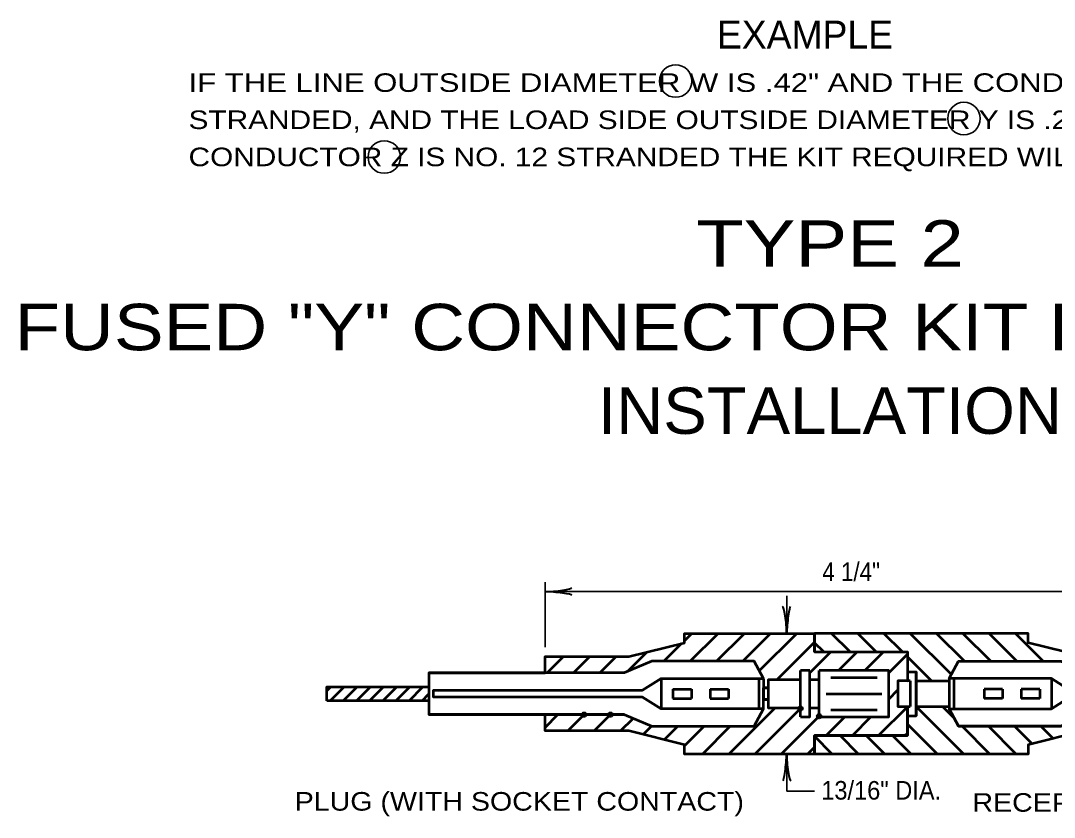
# Model space of a CAD drawing. Extents: x -1 to 679, y 0 to 440.
# Drawn here: x 256.4 to 367.7, y 153.2 to 239 of the extents above; entities that cross this region are included whole.
import ezdxf
from ezdxf.enums import TextEntityAlignment as Align

# ---------------------------------------------------------------- set-up
doc = ezdxf.new("R2010")
doc.units = 0
doc.header["$LTSCALE"] = 0.8
doc.header["$PDMODE"] = 32
doc.header["$PDSIZE"] = 0.4
doc.layers.add('1', color=7, linetype='Continuous', lineweight=53)

msp = doc.modelspace()

# ---------------------------------------------------------------- linework, layer by layer
at = {"layer": '1', "lineweight": 35}
for p, q in [((312.8991, 171.5513), (312.8991, 178.5513)), ((312.8991, 177.5513), (379.8991, 177.5513)), ((338.9009, 173.0513), (338.9009, 177.0949)), ((338.9009, 160.0513), (338.9009, 156.0513)), ((338.9009, 156.0513), (341.9009, 156.0513))]:
    msp.add_line(p, q, dxfattribs=at)
at = {"layer": '1'}
for p, q in [((327.8991, 172.2609), (328.6895, 173.0513)), ((328.5179, 170.0513), (331.5179, 173.0513)), ((331.3463, 170.0513), (334.3463, 173.0513)), ((334.1748, 170.0513), (337.1748, 173.0513)), ((335.9571, 169.0052), (340.0032, 173.0513)), ((341.8991, 171.0513), (341.8991, 173.0513)), ((345.7201, 171.0513), (343.7201, 173.0513)), ((348.5485, 171.0513), (346.5485, 173.0513)), ((351.3769, 171.0513), (349.3769, 173.0513)), ((356.6361, 168.6207), (352.2053, 173.0513)), ((358.0337, 170.0513), (355.0337, 173.0513)), ((360.8622, 170.0513), (357.8622, 173.0513)), ((363.6907, 170.0513), (360.6907, 173.0513)), ((366.5191, 170.0513), (363.5191, 173.0513)), ((325.6895, 170.0513), (327.6197, 171.9815)), ((337.8317, 168.0513), (341.8991, 172.1188)), ((342.8917, 171.0513), (341.8991, 172.0439)), ((313.1258, 168.8013), (314.8758, 170.5513)), ((315.9543, 168.8013), (317.7043, 170.5513)), ((318.7827, 168.8013), (320.5327, 170.5513)), ((321.7625, 168.9527), (323.8484, 171.0387)), ((341.3991, 168.7903), (343.6601, 171.0513)), ((344.4885, 169.0513), (346.4885, 171.0513)), ((347.3169, 169.0513), (349.3169, 171.0513)), ((349.8991, 168.8051), (351.8991, 170.8051)), ((354.5019, 167.9263), (351.8991, 170.5292)), ((300.3991, 168.8013), (300.3991, 164.3013)), ((325.3991, 168.1763), (325.3991, 164.9263)), ((335.8991, 168.1763), (335.8991, 164.9263)), ((336.3991, 168.1763), (336.3991, 165.9263)), ((336.3991, 168.1763), (336.3991, 165.9263)), ((340.3991, 164.0513), (340.3991, 169.0513)), ((341.3991, 169.0513), (340.3991, 169.0513)), ((340.3991, 164.0513), (340.3991, 169.0513)), ((341.3991, 169.0513), (340.3991, 169.0513)), ((342.3991, 168.0513), (341.3991, 168.0513)), ((342.3991, 168.0513), (341.3991, 168.0513)), ((342.3991, 164.0513), (342.3991, 169.0513)), ((342.3991, 164.0513), (342.3991, 169.0513)), ((343.6491, 168.3013), (348.6491, 168.3013)), ((356.3991, 168.1763), (356.3991, 164.9263)), ((356.8991, 168.1763), (356.8991, 164.9263)), ((367.3991, 168.1763), (367.3991, 164.9263)), ((289.3991, 166.852), (289.8484, 167.3013)), ((289.7627, 165.8013), (291.2627, 167.3013)), ((291.1768, 165.8013), (292.6768, 167.3013)), ((292.5911, 165.8013), (294.0911, 167.3013)), ((294.0053, 165.8013), (295.5053, 167.3013)), ((295.4195, 165.8013), (296.9195, 167.3013)), ((296.8338, 165.8013), (298.3338, 167.3013)), ((298.2479, 165.8013), (299.7479, 167.3013)), ((326.6491, 167.0513), (326.6491, 166.0513)), ((326.6491, 167.0513), (328.6491, 167.0513)), ((328.6491, 167.0513), (328.6491, 166.0513)), ((330.6491, 167.0513), (330.6491, 166.0513)), ((330.6491, 167.0513), (332.6491, 167.0513)), ((332.6491, 167.0513), (332.6491, 166.0513)), ((336.8991, 167.1763), (336.3991, 167.1763)), ((336.8991, 167.1763), (336.3991, 167.1763)), ((349.8991, 165.9766), (350.8832, 166.9607)), ((351.8488, 167.9263), (351.8991, 167.9766)), ((352.1908, 167.9263), (352.1908, 165.1763)), ((352.8259, 167.9263), (356.3991, 167.9263)), ((360.1491, 167.0513), (360.1491, 166.0513)), ((362.1491, 167.0513), (360.1491, 167.0513)), ((362.1491, 167.0513), (362.1491, 166.0513)), ((366.1491, 167.0513), (364.1491, 167.0513)), ((364.1491, 167.0513), (364.1491, 166.0513)), ((366.1491, 167.0513), (366.1491, 166.0513)), ((300.3991, 165.8013), (289.3991, 165.8013)), ((299.6622, 165.8013), (300.3991, 166.5383)), ((326.6491, 166.0513), (328.6491, 166.0513)), ((330.6491, 166.0513), (332.6491, 166.0513)), ((343.1491, 166.5513), (349.1491, 166.5513)), ((362.1491, 166.0513), (360.1491, 166.0513)), ((366.1491, 166.0513), (364.1491, 166.0513)), ((332.6601, 160.0513), (337.6601, 165.0513)), ((335.4885, 160.0513), (340.3991, 164.9619)), ((341.3991, 165.0513), (342.3991, 165.0513)), ((341.3991, 165.0513), (342.3991, 165.0513)), ((343.6491, 164.8013), (348.6491, 164.8013)), ((348.8023, 162.0513), (351.8991, 165.1482)), ((352.8259, 165.1763), (356.3991, 165.1763)), ((357.9563, 160.0513), (352.8313, 165.1763)), ((356.9584, 163.8777), (355.6597, 165.1763)), ((321.3991, 164.3013), (300.3991, 164.3013)), ((312.8991, 162.9177), (314.2827, 164.3013)), ((315.3611, 162.5513), (317.1111, 164.3013)), ((318.1895, 162.5513), (319.9395, 164.3013)), ((321.0179, 162.5513), (322.3653, 163.8988)), ((338.3169, 160.0513), (342.3991, 164.1335)), ((343.1453, 162.0513), (345.1453, 164.0513)), ((345.9738, 162.0513), (347.9738, 164.0513)), ((323.4569, 162.1619), (324.3619, 163.0668)), ((325.7197, 161.5962), (327.1748, 163.0513)), ((327.8991, 160.9472), (330.0032, 163.0513)), ((329.8317, 160.0513), (332.8317, 163.0513)), ((355.1278, 160.0513), (351.8991, 163.2801)), ((360.7847, 160.0513), (357.7847, 163.0513)), ((363.6131, 160.0513), (360.6131, 163.0513)), ((365.3331, 161.1598), (363.4416, 163.0513)), ((367.5958, 161.7255), (366.27, 163.0513)), ((343.8141, 160.0513), (341.8991, 161.9663)), ((346.6426, 160.0513), (344.6426, 162.0513)), ((349.471, 160.0513), (347.471, 162.0513)), ((352.2994, 160.0513), (350.2994, 162.0513)), ((351.6307, 162.0513), (351.8991, 162.3197)), ((341.1453, 160.0513), (341.8991, 160.8051))]:
    msp.add_line(p, q, dxfattribs=at)
for points in [[(312.8991, 168.8013), (312.8991, 170.5513), (321.8991, 170.5513), (327.8991, 172.0513), (327.8991, 173.0513), (341.8991, 173.0513), (341.8991, 171.0513), (351.8991, 171.0513), (351.8991, 167.9263)], [(312.8991, 168.8013), (312.8991, 170.5513), (321.8991, 170.5513), (327.8991, 172.0513), (327.8991, 173.0513), (341.8991, 173.0513), (341.8991, 171.0513), (351.8991, 171.0513), (351.8991, 167.9263)], [(379.8991, 168.8013), (379.8991, 170.5513), (370.8991, 170.5513), (364.8991, 172.0513), (364.8991, 173.0513), (341.8991, 173.0513), (341.8991, 171.0513), (351.8991, 171.0513), (351.8991, 167.9263)], [(336.3991, 168.1763), (335.3991, 170.0513), (324.3991, 170.0513), (321.3991, 168.8013), (300.3991, 168.8013), (312.8991, 168.8013)], [(336.3991, 168.1763), (335.3991, 170.0513), (324.3991, 170.0513), (321.3991, 168.8013), (300.3991, 168.8013), (312.8991, 168.8013)], [(356.3991, 168.1763), (357.3991, 170.0513), (368.3991, 170.0513), (371.3991, 168.8013), (392.3991, 168.8013), (379.8991, 168.8013)], [(340.3991, 168.0513), (336.8991, 168.0513), (336.8991, 165.9263)], [(340.3991, 168.0513), (336.8991, 168.0513), (336.8991, 165.9263)], [(340.3991, 164.0513), (341.3991, 164.0513), (341.3991, 169.0513)], [(340.3991, 164.0513), (341.3991, 164.0513), (341.3991, 169.0513)], [(342.3991, 164.0513), (349.8991, 164.0513), (349.8991, 169.0513), (342.3991, 169.0513)], [(342.3991, 164.0513), (349.8991, 164.0513), (349.8991, 169.0513), (342.3991, 169.0513)], [(351.8991, 164.1763), (352.8259, 164.1763), (352.8259, 168.9263)], [(351.8991, 168.9263), (352.8259, 168.9263), (352.8259, 164.1763)], [(289.3991, 165.8013), (289.3991, 167.3013), (300.3991, 167.3013)], [(352.1908, 167.9263), (350.8832, 167.9263), (350.8832, 165.1763), (352.1908, 165.1763)], [(352.1908, 167.9263), (350.8832, 167.9263), (350.8832, 165.1763), (352.1908, 165.1763)], [(321.3991, 164.3013), (324.3991, 163.0513), (335.3991, 163.0513), (336.3991, 164.9263), (336.3991, 165.9263), (336.8991, 165.9263), (336.8991, 165.0513), (340.3991, 165.0513)], [(321.3991, 164.3013), (324.3991, 163.0513), (335.3991, 163.0513), (336.3991, 164.9263), (336.3991, 165.9263), (336.8991, 165.9263), (336.8991, 165.0513), (340.3991, 165.0513)], [(351.8991, 165.1763), (351.8991, 162.0513), (341.8991, 162.0513), (341.8991, 160.0513), (327.8991, 160.0513), (327.8991, 161.0513), (321.8991, 162.5513), (312.8991, 162.5513), (312.8991, 164.3013)], [(351.8991, 165.1763), (351.8991, 162.0513), (341.8991, 162.0513), (341.8991, 160.0513), (327.8991, 160.0513), (327.8991, 161.0513), (321.8991, 162.5513), (312.8991, 162.5513), (312.8991, 164.3013)], [(379.8991, 164.3013), (379.8991, 162.5513), (370.8991, 162.5513), (364.8991, 161.0513), (364.8991, 160.0513), (341.8991, 160.0513), (341.8991, 162.0513), (351.8991, 162.0513), (351.8991, 165.1763)], [(356.3991, 164.9263), (357.3991, 163.0513), (368.3991, 163.0513), (371.3991, 164.3013), (392.3991, 164.3013), (379.8991, 164.3013)], [(321.3991, 164.3013), (300.3991, 164.3013), (321.3991, 164.3013)]]:
    msp.add_lwpolyline(points, dxfattribs=at)
for points in [[(336.3991, 168.1763), (335.3991, 170.0513), (324.3991, 170.0513), (321.3991, 168.8013), (300.3991, 168.8013), (300.3991, 164.3013), (321.3991, 164.3013), (324.3991, 163.0513), (335.3991, 163.0513), (336.3991, 164.9263), (325.3991, 164.9263), (323.3991, 166.1763), (300.8991, 166.1763), (300.8991, 166.9263), (323.3991, 166.9263), (325.3991, 168.1763)], [(356.3991, 168.1763), (357.3991, 170.0513), (368.3991, 170.0513), (371.3991, 168.8013), (392.3991, 168.8013), (392.3991, 164.3013), (371.3991, 164.3013), (368.3991, 163.0513), (357.3991, 163.0513), (356.3991, 164.9263), (367.3991, 164.9263), (369.3991, 166.1763), (391.8991, 166.1763), (391.8991, 166.9263), (369.3991, 166.9263), (367.3991, 168.1763)], [(336.3991, 165.9263), (336.3991, 167.1763), (336.8991, 167.1763), (336.8991, 165.9263)]]:
    msp.add_lwpolyline(points, close=True, dxfattribs=at)
at = {"layer": '1', "lineweight": 35}
for centre in [(326.9513, 232.5219), (357.9822, 228.4878), (295.5842, 224.3414)]:
    msp.add_circle(centre, 1.75, dxfattribs=at)
at = {"layer": '1', "lineweight": 40}
for centre, major_axis, ratio, start_param, end_param in [((314.0196, 177.3397), (-1.7565, 0.1757), 0.07063, 3.14071475, 5.41810995), ((314.0196, 177.3397), (-1.7565, 0.1757), 0.07063, 3.14071475, 5.41810995), ((313.9903, 177.8276), (-1.7857, -0.1562), 0.122415, 0.89635335, 3.14159265), ((313.9903, 177.8276), (-1.7857, -0.1562), 0.122415, 0.89635335, 3.14159265), ((338.6246, 174.1425), (0.1562, -1.7857), 0.122415, 0.89635335, 3.14159265), ((339.1125, 174.1718), (-0.1757, -1.7565), 0.07063, 3.14071475, 5.41810995), ((338.6893, 158.9308), (0.1757, 1.7565), 0.07063, 3.14071475, 5.41810995), ((339.1772, 158.9601), (-0.1562, 1.7857), 0.122415, 0.89635335, 3.14159265)]:
    msp.add_ellipse(centre, major_axis=major_axis, ratio=ratio, start_param=start_param, end_param=end_param, dxfattribs=at)
at = {"layer": '1'}
for p in [(340.3991, 164.9619), (317.1111, 164.3013), (319.9395, 164.3013), (342.3991, 164.1335)]:
    msp.add_point(p, dxfattribs=at)

# ---------------------------------------------------------------- texts
msp.add_text('EXAMPLE', height=3, dxfattribs=at).set_placement((331.3949, 236.0256))
for s, width, p in [('IF THE LINE OUTSIDE DIAMETER W IS .42" AND THE CONDUCTOR X IS NO. 6', 1.25, (274.5172, 231.3548)), ('STRANDED, AND THE LOAD SIDE OUTSIDE DIAMETER Y IS .29" AND THE', 1.2, (274.5172, 227.3548)), ('CONDUCTOR Z IS NO. 12 STRANDED THE KIT REQUIRED WILL BE II-DB3-C6.', 1.2, (274.5172, 223.3548)), ('4 1/4"', 0.9, (342.7398, 178.6865)), ('13/16" DIA.', 0.95, (342.621, 155.1532)), ('PLUG (WITH SOCKET CONTACT)', 1.15, (285.9456, 153.9647)), ('RECEPTACLE (WITH PIN CONTACT)', 1.15, (358.8988, 153.8458))]:
    msp.add_text(s, height=2, dxfattribs=dict(at, width=width)).set_placement(p)
for s, width, p in [('TYPE 2', 1.25, (343.5637, 212.536)), ('FUSED "Y" CONNECTOR KIT FOR POLE BASE', 1.2, (343.5636, 203.536)), ('INSTALLATION', 1.05, (343.5636, 194.536))]:
    msp.add_text(s, height=5, dxfattribs=dict(at, width=width)).set_placement(p, align=Align.CENTER)

doc.saveas('drawing.dxf')
